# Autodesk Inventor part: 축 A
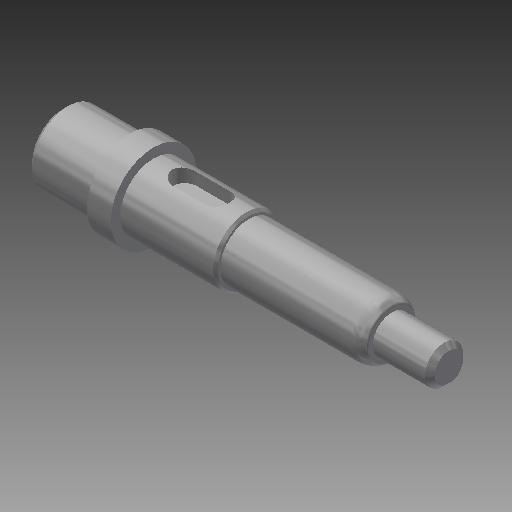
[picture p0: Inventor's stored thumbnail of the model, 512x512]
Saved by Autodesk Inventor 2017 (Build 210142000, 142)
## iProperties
Created: 2020-04
Part Number: 축 A
Material: 강철, 연강
Document SubType Name: Modeling
Designer: mduedu
Density: 7.86 g/cm^3
Appearance: 강철
Mass: 83.1595 g
Surface Area: 37.6208 cm^2
Volume: 10.5801 cm^3
Author: mduedu
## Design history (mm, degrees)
sketch "스케치1"
  geometry: L1 (0, 0)-(14, 0); L2 (14, 0)-(14, 7.5); L3 (14, 7.5)-(0, 7.5); L4 (0, 7.5)-(0, 0); L5 (14, 0)-(19, 0); L6 (19, 0)-(19, 9); L7 (19, 9)-(14, 9); L8 (14, 9)-(14, 0); L9 (19, 0)-(39, 0); L10 (39, 0)-(39, 7); L11 (39, 7)-(19, 7); L12 (19, 7)-(19, 0); L13 (39, 0)-(69, 0); L14 (69, 0)-(69, 6); L15 (69, 6)-(39, 6); L16 (39, 6)-(39, 0); L17 (69, 0)-(81, 0); L18 (81, 0)-(81, 4); L19 (81, 4)-(69, 4); L20 (69, 4)-(69, 0)
  constraints: 40 end point, 10 parallel, 5 horizontal, 5 perpendicular
  dimensions: "d0" = 81 distance between parallel lines of L18 L4; "d2" = 14 distance of L2.end L3.end; "d3" = 5 distance of L6.end L7.end; "d4" = 12 distance of L18.end L19.end; "d5" = 8 diameter of L19 L17; "d6" = 12 diameter of L15 L13; "d7" = 14 diameter of L11 L9; "d8" = 15 diameter of L3 L1; "d9" = 18 diameter of L7 L5; "d10" = 42 distance between parallel lines of L10 L18
revolve "회전1" sketch "스케치1" stored, may be unused: angle "d11" = 90 deg
sketch "스케치2"
  geometry: L1 (0, -7.5)-(0, 7.5) reference; L2 (0, 7.5)-(14, 7.5) reference; L3 (14, 7.5)-(14, 9) reference; L4 (14, 9)-(19, 9) reference; L5 (19, 9)-(19, 7) reference; L6 (19, 7)-(39, 7) reference; L7 (39, 7)-(39, 6) reference; L8 (39, 6)-(69, 6) reference; L9 (69, 6)-(69, 4) reference; L10 (69, 4)-(81, 4) reference; L11 (81, 4)-(81, -4) reference; L12 (81, -4)-(69, -4) reference; L13 (69, -4)-(69, -6) reference; L14 (69, -6)-(39, -6) reference; L15 (39, -6)-(39, -7) reference; L16 (39, -7)-(19, -7) reference; L17 (19, -7)-(19, -9) reference; L18 (19, -9)-(14, -9) reference; L19 (14, -9)-(14, -7.5) reference; L20 (14, -7.5)-(0, -7.5) reference; L21 (81, -4)-(73, -4); L22 (73, -4)-(73, -2.8); L23 (73, -2.8)-(81, -2.8); L24 (81, -2.8)-(81, -4); 1 further point
  constraints: 8 end point, 2 parallel, 1 horizontal, 1 perpendicular
  dimensions: "d12" = 8 distance of L22.end L23.end; "d13" = 1.2 distance of L21.end L22.end
extrude "돌출1" cut sketch "스케치2" stored distance "d14" = 2; taper "d15" = 0 deg
fillet "모깎기1" dims "d16" = 1
sketch "스케치3"
  geometry: L1 (0, -7.5)-(0, 7.5) reference; L2 (0, 7.5)-(14, 7.5) reference; L3 (14, 7.5)-(14, 9) reference; L4 (14, 9)-(19, 9) reference; L5 (19, 9)-(19, 7) reference; L6 (19, 7)-(39, 7) reference; L7 (39, 7)-(39, 6) reference; L8 (39, 6)-(69, 6) reference; L9 (69, 6)-(69, 4) reference; L10 (69, 4)-(81, 4) reference; L11 (81, 4)-(81, -2.8) reference; L12 (81, -2.8)-(73, -2.8) reference; L13 (73, -2.8)-(73, -4) reference; L14 (73, -4)-(69, -4) reference; L15 (69, -4)-(69, -6) reference; L16 (69, -6)-(39, -6) reference; L17 (39, -6)-(39, -7) reference; L18 (39, -7)-(19, -7) reference; L19 (19, -7)-(19, -9) reference; L20 (19, -9)-(14, -9) reference; L21 (14, -9)-(14, -7.5) reference; L22 (14, -7.5)-(0, -7.5) reference; L23 (23, 7)-(35, 7); L24 (35, 7)-(35, 4); L25 (35, 4)-(23, 4); L26 (23, 4)-(23, 7); 1 further point
  constraints: 8 end point, 2 parallel, 1 horizontal, 1 perpendicular, 1 point on line
  dimensions: "d17" = 12 distance of L24.end L25.end; "d18" = 3 distance of L23.end L24.end; "d19" = 4 distance from line of L26 L4.end
extrude "돌출2" cut sketch "스케치3" stored distance "d20" = 5; taper "d21" = 0 deg
fillet "모깎기2" dims "d22" = 2.5
chamfer "모따기1" distance "d23" = 1; stored, may be unused: second distance "d24" = 2, angle "d25" = 45 deg
chamfer "모따기2" distance "d26" = 0.5; stored, may be unused: second distance "d27" = 2, angle "d28" = 45 deg
fillet "모깎기3" dims "d29" = 0.3
chamfer "모따기3" distance "d30" = 1.56; stored, may be unused: second distance "d31" = 2, angle "d32" = 30 deg
fillet "모깎기4" dims "d33" = 4, "d34" = 0.5
node "솔리드1"
node "절단 모서리 투영1"
node "절단 모서리 투영2"
